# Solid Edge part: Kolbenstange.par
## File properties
Username: bmolnar
Dokumentum tartalom típus: 0
Author: bmolnar
Last saved by: bmolnar
Revision: 80
Sűrűség: 0,000 kg/m^3
Pontosság: 0,990
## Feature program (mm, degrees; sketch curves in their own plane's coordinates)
base feature "unnamed BaseFeature 1"
sketch for "unnamed Protrusion 1" plane through (-0.0012, 0, -16.4) normal (0, 0, -1) x-axis (0, -1, 0)
  circle centre (0, -0.0012) radius 16
extrude "unnamed Protrusion 1" add finite 8.35 along +normal
sketch for "Furat_1" plane through (0, 0, 18.9) normal (0, 0, 1) x-axis (0, 1, 0)
  hole centre (0, 0) bore radius 2.4585
hole "Furat_1" nominal diameter 6 finite  VBottomAngle = 118 deg; ThreadDepth = 12.5 mm
chamfer "Letörés_1" setback 0.5  SetBackValue2 = 45 deg
sketch for "Kihúzás_3" #1 plane through (0, 0, -16.4) normal (0, 0, 1) x-axis (0, 1, 0)
  circle centre (0, 0) radius 6
sketch for "Kihúzás_3" #2 plane through (0, 0, -16.4) normal (0, 0, 1) x-axis (0, 1, 0)
  circle centre (0, 0) radius 16
extrude "Kihúzás_3" add finite 22.65 along +normal
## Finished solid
Body 1: solid body, 17 faces, 23 edges, 8 vertices.
  Faces by surface: plane 7, cylinder 5, cone 3, torus 2
  Edges by curve: circle 13, line 6, curve on surface 2, ellipse 2
Bounding box of the edges (mm; curved faces can reach further): 32.000 x 32.000 x 46.150, from (-16, -16, -24.75) to (16, 16, 21.4).
Cylindrical faces by radius (mm): R2.4585 x2, R3.125 x1, R6 x1, R16 x1
Conical faces (half-angle, radius in mm at the cone's reference point): 45 deg R2.9585 x1, 45 deg R3.225 x1, 59 deg R2.4585 x1
Toroidal faces (ring radius, tube radius in mm): R2.925 r0.2 x1, R4.7 r1.3 x1
Planar faces by outward normal: +x 1, +z 2, -x 1, -z 1, oblique 2
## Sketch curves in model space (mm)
circle centre (0, 0, -16.4) radius 16
circle centre (0, 0, -16.4) radius 6
circle centre (0, 0, -16.4) radius 16
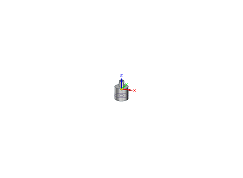
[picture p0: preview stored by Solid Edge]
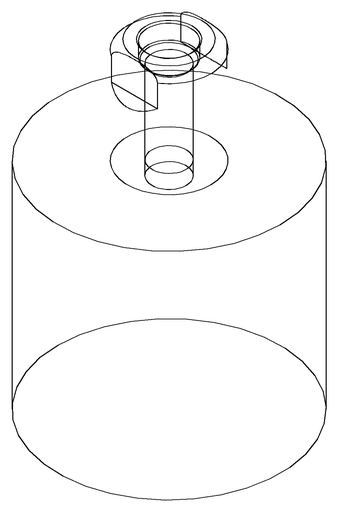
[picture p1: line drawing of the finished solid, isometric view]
